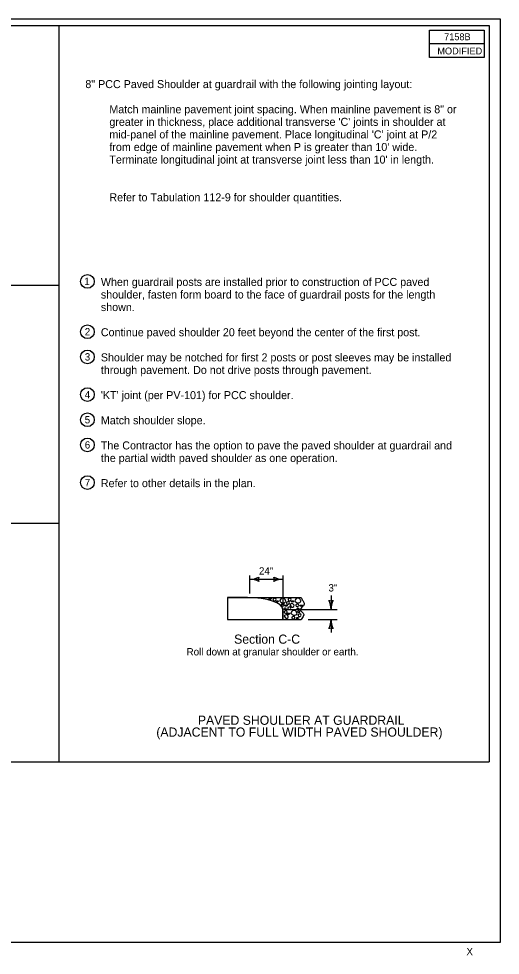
# Model space of a CAD drawing. Extents: x 9538 to 81668, y 7600 to 11751.
# Drawn here: x 30215 to 31268, y 7896 to 9944 of the extents above; entities that cross this region are included whole.
import ezdxf

# ---------------------------------------------------------------- set-up
doc = ezdxf.new("R2010")
doc.units = 0
for name, color, linetype in [('Default', 7, 'Continuous'), ('DsnShtMinorGrid12', 7, 'Continuous'), ('DsnShtMinorGrid13', 7, 'Continuous'), ('dsnStdBlockNotModified', 7, 'Continuous'), ('dsnStdCells', 7, 'Continuous'), ('dsnStdDimension', 7, 'Continuous'), ('dsnStdNameDate', 7, 'Continuous'), ('dsnStdNote', 7, 'Continuous'), ('dsnStdShading', 7, 'Continuous'), ('dsnStdTable', 7, 'Continuous'), ('Level 9', 7, 'Continuous')]:
    doc.layers.add(name, color=color, linetype=linetype)

msp = doc.modelspace()

# ---------------------------------------------------------------- linework, layer by layer
at = {"layer": 'Default'}
msp.add_lwpolyline([(28132.6, 9944), (31267.6, 9944), (31267.6, 7924), (28132.6, 7924)], close=True, dxfattribs=at)
at = {"layer": 'DsnShtMinorGrid12'}
for points in [[(30764.3, 8674.1), (30765.2, 8673.9), (30765.7, 8673.9), (30768.1, 8676.3), (30764.1, 8677.1), (30760.6, 8675), (30763.5, 8674.3), (30764.3, 8674.1)], [(30770.7, 8674.6), (30770.8, 8675.1), (30771.1, 8675), (30775.7, 8677.6), (30778.1, 8674.4), (30776, 8670.4), (30770.9, 8671.5), (30770.7, 8674), (30770.7, 8674.6)], [(30779.9, 8668.6), (30780.8, 8668.4), (30781.3, 8668.4), (30783.7, 8670.8), (30779.7, 8671.6), (30776.2, 8669.5), (30779.1, 8668.7), (30779.9, 8668.6)], [(30785.6, 8670.8), (30785.3, 8671.3), (30785.9, 8670.9), (30787.8, 8677.4), (30796.1, 8677.6), (30798.7, 8670.4), (30799, 8669.6), (30794.2, 8665.8), (30787.5, 8668), (30785.9, 8670.3), (30785.6, 8670.8)], [(30789.1, 8663.3), (30789.2, 8663.9), (30789.5, 8663.7), (30794.1, 8666.4), (30796.5, 8663.2), (30794.3, 8659.2), (30789.3, 8660.2), (30789.1, 8662.7), (30789.1, 8663.3)], [(30800.1, 8667.4), (30800.2, 8668), (30800.5, 8667.8), (30805.1, 8670.5), (30807.5, 8667.3), (30805.4, 8663.2), (30800.3, 8664.3), (30800.1, 8666.8), (30800.1, 8667.4)], [(30803.7, 8674.6), (30803.7, 8675.1), (30804.1, 8675), (30808.6, 8677.6), (30811, 8674.4), (30808.9, 8670.4), (30803.8, 8671.5), (30803.6, 8674), (30803.7, 8674.6)], [(30808.2, 8661.4), (30807.6, 8662.5), (30807.8, 8662.9), (30812.4, 8665.8), (30816.4, 8664), (30817.5, 8658.6), (30811.3, 8655.9), (30808.8, 8660.2), (30808.2, 8661.4)], [(30812.9, 8668.6), (30813.7, 8668.4), (30814.3, 8668.4), (30816.7, 8670.8), (30812.6, 8671.6), (30809.2, 8669.5), (30812, 8668.7), (30812.9, 8668.6)], [(30818.5, 8670.8), (30818.3, 8671.3), (30818.8, 8670.9), (30820.7, 8677.4), (30829, 8677.6), (30831.7, 8670.4), (30831.9, 8669.6), (30827.1, 8665.8), (30820.4, 8668), (30818.8, 8670.3), (30818.5, 8670.8)], [(30820.4, 8662), (30820.5, 8662.6), (30820.8, 8662.4), (30825.4, 8665.1), (30827.8, 8661.9), (30825.6, 8657.9), (30820.5, 8658.9), (30820.4, 8661.4), (30820.4, 8662)], [(30794.5, 8653.6), (30794.1, 8654.1), (30794.5, 8654.5), (30798.7, 8655.8), (30800.1, 8652.3), (30796.9, 8651.5), (30794.9, 8653.2), (30794.5, 8653.6)], [(30795.3, 8647.4), (30795.3, 8648), (30795.7, 8647.8), (30800.2, 8650.5), (30802.6, 8647.3), (30800.5, 8643.3), (30795.4, 8644.3), (30795.2, 8646.8), (30795.3, 8647.4)], [(30799.2, 8659.3), (30800.1, 8659.1), (30800.6, 8659.1), (30803, 8661.6), (30799, 8662.4), (30795.5, 8660.2), (30798.4, 8659.5), (30799.2, 8659.3)], [(30804.5, 8641.4), (30805.3, 8641.3), (30805.8, 8641.3), (30808.2, 8643.7), (30804.2, 8644.5), (30800.7, 8642.3), (30803.6, 8641.6), (30804.5, 8641.4)], [(30803, 8655.6), (30803, 8656.2), (30803.4, 8656), (30808, 8658.7), (30810.4, 8655.4), (30808.2, 8651.4), (30803.1, 8652.5), (30803, 8655), (30803, 8655.6)], [(30810.1, 8643.7), (30809.9, 8644.2), (30810.4, 8643.8), (30812.3, 8650.2), (30820.6, 8650.5), (30823.3, 8643.3), (30823.5, 8642.5), (30818.7, 8638.7), (30812, 8640.9), (30810.4, 8643.2), (30810.1, 8643.7)], [(30823.1, 8653.2), (30822.7, 8653.7), (30823.1, 8654.1), (30827.4, 8655.4), (30828.7, 8651.9), (30825.5, 8651.1), (30823.5, 8652.7), (30823.1, 8653.2)], [(30824.4, 8647.1), (30824, 8647.6), (30824.4, 8648), (30828.7, 8649.3), (30830, 8645.8), (30826.8, 8645), (30824.8, 8646.6), (30824.4, 8647.1)], [(30832.2, 8659.3), (30833, 8659.1), (30833.5, 8659.1), (30836, 8661.6), (30831.9, 8662.4), (30828.5, 8660.2), (30831.3, 8659.5), (30832.2, 8659.3)], [(30795.7, 8636.9), (30795.1, 8638), (30795.3, 8638.4), (30799.8, 8641.3), (30803.8, 8639.4), (30804.9, 8634.1), (30798.8, 8631.4), (30796.3, 8635.7), (30795.7, 8636.9)], [(30812, 8634.9), (30812, 8635.5), (30812.4, 8635.3), (30817, 8638), (30819.4, 8634.7), (30817.2, 8630.7), (30812.1, 8631.8), (30812, 8634.3), (30812, 8634.9)], [(30823.7, 8632.2), (30824.6, 8632), (30825.1, 8632), (30827.5, 8634.4), (30823.5, 8635.2), (30820, 8633.1), (30822.9, 8632.4), (30823.7, 8632.2)], [(30825.6, 8640.3), (30825.6, 8640.9), (30826, 8640.7), (30830.5, 8643.4), (30832.9, 8640.2), (30830.8, 8636.2), (30825.7, 8637.2), (30825.5, 8639.7), (30825.6, 8640.3)]]:
    msp.add_open_spline(points, degree=3, dxfattribs=at)
at = {"layer": 'DsnShtMinorGrid13'}
for centre in [(30365, 9369.6), (30365, 9259.6), (30365, 9204.6), (30365, 9122.1), (30365, 9067.1), (30365, 9012.1), (30365, 8929.6)]:
    msp.add_circle(centre, 15, dxfattribs=at)
at = {"layer": 'dsnStdCells'}
for p, q in [((30714.7, 8678.3), (30671.6, 8678.3)), ((30671.6, 8678.3), (30671.6, 8630.3)), ((30792.5, 8630.3), (30792.5, 8652.1)), ((30671.6, 8630.3), (30792.5, 8630.3))]:
    msp.add_line(p, q, dxfattribs=at)
msp.add_lwpolyline([(30714.7, 8678.3), (30714.7, 8678.3)], dxfattribs=at)
msp.add_ellipse((30714.7, 8652.1), major_axis=(77.9, 0), ratio=0.335273, start_param=0, end_param=1.570796, dxfattribs=at)
at = {"layer": 'dsnStdDimension'}
for p, q in [((30720, 8686.8), (30720, 8726.2)), ((30792.5, 8726.2), (30792.5, 8662.7)), ((30720, 8718.2), (30792.5, 8718.2)), ((30897.6, 8683.1), (30897.6, 8652.1)), ((30799.4, 8652.1), (30911.4, 8652.1)), ((30847.3, 8630.3), (30911.4, 8630.3)), ((30897.6, 8630.3), (30897.6, 8601.7))]:
    msp.add_line(p, q, dxfattribs=at)
for centre, radius, start, end in [((30720, 8760.7), 42.5, 270, 298.0725), ((30720, 8675.7), 42.5, 61.9275, 90), ((30755.6, 8718.2), 16.4, 162.2666, 197.7334), ((30756.9, 8718.2), 16.4, 342.2666, 17.7334), ((30792.5, 8760.7), 42.5, 241.9275, 270), ((30792.5, 8675.7), 42.5, 90, 118.0725), ((30897.6, 8687.8), 16.4, 252.2666, 287.7334), ((30855.1, 8652.1), 42.5, 0, 28.0725), ((30940.1, 8652.1), 42.5, 151.9275, 180), ((30855.1, 8630.3), 42.5, 331.9275, 360), ((30940.1, 8630.3), 42.5, 180, 208.0725), ((30897.6, 8594.7), 16.4, 72.2666, 107.7334)]:
    msp.add_arc(centre, radius, start, end, dxfattribs=at)
at = {"layer": 'dsnStdNameDate'}
for p, q in [((30303.1, 8319), (30303.1, 9929)), ((30303.1, 9361), (28147.6, 9361)), ((30303.1, 8840), (28147.6, 8840))]:
    msp.add_line(p, q, dxfattribs=at)
at = {"layer": 'dsnStdShading'}
for p, q in [((28147.6, 9929), (31243.2, 9929)), ((31243.2, 9929), (31243.2, 8319)), ((28147.6, 8319), (31243.2, 8319))]:
    msp.add_line(p, q, dxfattribs=at)
at = {"layer": 'dsnStdTable'}
for p, q in [((31243.2, 9929), (31243.2, 9929)), ((30671.6, 8678.3), (30671.6, 8630.3)), ((30671.6, 8678.3), (30714.7, 8678.3)), ((30714.7, 8678.3), (30832.4, 8678.3)), ((30792.5, 8652.1), (30792.5, 8630.3)), ((30671.6, 8630.3), (30792.5, 8630.3)), ((30792.5, 8630.3), (30832.4, 8630.3))]:
    msp.add_line(p, q, dxfattribs=at)
msp.add_lwpolyline([(31232.4, 9919), (31232.4, 9859), (31112.7, 9859), (31112.7, 9919), (31232.4, 9919), (31232.4, 9889), (31112.7, 9889)], dxfattribs=at)
msp.add_ellipse((30714.7, 8652.1), major_axis=(77.9, 0), ratio=0.335273, start_param=0, end_param=1.570796, dxfattribs=at)
msp.add_spline([(30832.4, 8678.3), (30833.8, 8675.1), (30835.7, 8671.9), (30837.5, 8668.9), (30839, 8665.8), (30839.1, 8664.1), (30838.4, 8662.3), (30835.6, 8658.8), (30832.4, 8655.3), (30831.3, 8653.6), (30831, 8652.7), (30830.9, 8651.8), (30830.9, 8651.4), (30831.2, 8650.2), (30832.2, 8648.7), (30835.2, 8645.5), (30837.6, 8642.3), (30838.1, 8640.7), (30838, 8639.9), (30837.9, 8639.5), (30837.7, 8639.1), (30832.4, 8630.4)], degree=3, dxfattribs=at)

# ---------------------------------------------------------------- texts
at = {"layer": 'DsnShtMinorGrid13'}
for s, height, p in [('8" PCC Paved Shoulder at guardrail with the following jointing layout:', 17.5, (30360.6, 9792.3)), ('Match mainline pavement joint spacing. When mainline pavement is 8" or ', 17.5, (30413.1, 9737.3)), ("greater in thickness, place additional transverse 'C' joints in shoulder at ", 17.5, (30413.1, 9709.8)), ("mid-panel of the mainline pavement. Place longitudinal 'C' joint at P/2 ", 17.5, (30413.1, 9682.3)), ("from edge of mainline pavement when P is greater than 10' wide. ", 17.5, (30413.1, 9654.8)), ("Terminate longitudinal joint at transverse joint less than 10' in length.", 17.5, (30413.1, 9627.3)), ('Refer to Tabulation 112-9 for shoulder quantities.', 17.5, (30413.1, 9544.8)), ('1', 16, (30358.2, 9361.6)), ('When guardrail posts are installed prior to construction of PCC paved ', 17.5, (30394.5, 9359.7)), ('shoulder, fasten form board to the face of guardrail posts for the length ', 17.5, (30394.5, 9332.2)), ('shown.', 17.5, (30394.5, 9304.7)), ('2', 16, (30359.3, 9251.6)), ('Continue paved shoulder 20 feet beyond the center of the first post.', 17.5, (30394.5, 9249.7)), ('3', 16, (30359.3, 9196.6)), ('Shoulder may be notched for first 2 posts or post sleeves may be installed ', 17.5, (30394.5, 9194.7)), ('through pavement. Do not drive posts through pavement.', 17.5, (30394.5, 9167.2)), ('4', 16, (30359.3, 9114.1)), ("'KT' joint (per PV-101) for PCC shoulder.", 17.5, (30394.5, 9112.2)), ('5', 16, (30359.2, 9059.1)), ('Match shoulder slope.', 17.5, (30394.5, 9057.2)), ('6', 16, (30359.3, 9004.1)), ('The Contractor has the option to pave the paved shoulder at guardrail and ', 17.5, (30394.5, 9002.2)), ('the partial width paved shoulder as one operation.', 17.5, (30394.5, 8974.7)), ('7', 16, (30359.3, 8921.6)), ('Refer to other details in the plan.', 17.5, (30394.5, 8919.7))]:
    msp.add_text(s, height=height, dxfattribs=at).set_placement(p)
at = {"layer": 'dsnStdBlockNotModified'}
msp.add_text('X', height=16, dxfattribs=at).set_placement((31193.6, 7896))
at = {"layer": 'dsnStdDimension'}
for s, p in [("24''", (30740.1, 8728.5)), ("3'' ", (30892, 8691.5))]:
    msp.add_text(s, height=16, dxfattribs=at).set_placement(p)
at = {"layer": 'dsnStdNote'}
for s, height, p in [('Section C-C', 20, (30685.8, 8577.3)), ('Roll down at granular shoulder or earth.', 16, (30581.9, 8551.7)), ('PAVED SHOULDER AT GUARDRAIL', 20, (30606.5, 8400)), ('(ADJACENT TO FULL WIDTH PAVED SHOULDER)', 20, (30515.7, 8374.1))]:
    msp.add_text(s, height=height, dxfattribs=at).set_placement(p)
at = {"layer": 'Level 9'}
for s, p in [('7158B', (31144.8, 9897)), ('MODIFIED', (31130, 9866))]:
    msp.add_text(s, height=15, dxfattribs=at).set_placement(p)

doc.saveas('drawing.dxf')
